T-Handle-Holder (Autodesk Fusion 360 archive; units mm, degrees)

design "T-Handle-Holder" references "Base"
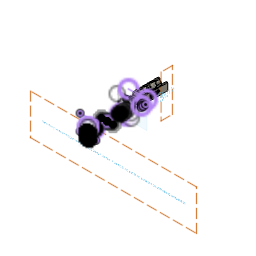
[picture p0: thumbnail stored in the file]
parameter "handle_width" = 30
parameter "stick_diameter" = 7
parameter "hole_bottom_diameter" = 17
parameter "end_front_diameter" = 23
parameter "end_back_diameter" = 25
parameter "stick_center_to_back_end_distance" = 50
parameter "stick_center_to_front_end_distance" = 50
parameter "bottom_hole_to_front_bottom_ditance" = 15
component_insert "Component Insert"
sketch "Reference" plane through (0, 55.6118, 0) normal (0, 1, 0) x axis (-1, 0, 0)
  line L1 (0, 47.0059) -> (0, -10)
  line L2 (-48, 47.0059) -> (0, 47.0059)
  line L3 (-48, -10) -> (-48, 47.0059)
  line L4 (0, -10) -> (-48, -10)
  line L5 (-48, 60) -> (0, 60)
sketch "Bottom" plane through (0, 0, 0) normal (0, 0, 1) x axis (1, 0, 0)
  circle C1 centre (0, 0) radius 8.5
  circle C2 centre (0, 0) radius 3.5
  point P1 (0, 0)
  point P2 (0, 0)
  point P3 (0, 0)
  coincident P1 P2
  coincident P1 P3
  dimension "d5" diameter C1 = 17 (= "hole_bottom_diameter")
  dimension "d6" diameter C2 = 7 (= "stick_diameter")
work_plane "WorkPlane1" sketch "Bottom" AlongDistance 15 (= "bottom_hole_to_front_bottom_ditance")
sketch "Center" plane through (0, 0, 15) normal (0, 0, 1) x axis (1, 0, 0)
  line L1 (0, -50) -> (0, 0)
  line L2 (0, 50) -> (0, 0)
  line L3 (0, -33) -> (0, 0)
  line L4 (0, 33) -> (0, 0)
  line L5 (-15, 0) -> (0, 0)
  curve K1 (0, 33) -> (0, -33)
  curve K2 (-4, -33) -> (4, -33)
  curve K3 (4, 33) -> (-4, 33)
  curve K4 (0, 33) -> (0, -33)
  curve K5 (4, -33) -> (-4, -33)
  curve K6 (-4, 33) -> (4, 33)
  circle C1 centre (0, 0) radius 15
  point P2 (0, 0)
  point P3 (0, 0)
  point P6 (0, 0)
  point P8 (0, 0)
  point P7 (0, -33)
  point P9 (0, 33)
  point P15 (0, -33)
  point P17 (0, 33)
  point P10 (-15, 0)
  point P16 (15, 0)
  point P11 (4, -33)
  point P18 (-4, -33)
  point P12 (-4, -33)
  point P19 (4, -33)
  point P13 (-4, 33)
  point P20 (4, 33)
  point P14 (4, 33)
  point P21 (-4, 33)
  point P4 (0, -50)
  point P5 (0, 50)
  coincident P2 P3
  vertical L1
  parallel L1 L2
  coincident P2 P6
  parallel L1 L3
  coincident P2 P8
  parallel L2 L4
  perpendicular L1 L5
  midpoint P7 K2
  midpoint P9 K3
  symmetric L1 P7 P15
  symmetric L1 P9 P17
  symmetric L1 P10 P16
  symmetric L1 P11 P18
  symmetric L1 P12 P19
  symmetric L1 P13 P20
  symmetric L1 P14 P21
  dimension "d13" distance P3 P4 = 50 (= "stick_center_to_front_end_distance")
  dimension "d14" distance P3 P5 = 50 (= "stick_center_to_back_end_distance")
  dimension "d19" diameter C1 = 30 (= "handle_width")
  dimension "d65" distance P3 P7 = 33 (= "stick_center_to_front_end_distance * 0.66")
  dimension "d66" distance P8 P9 = 33 (= "stick_center_to_back_end_distance * 0.66")
  dimension "d67" distance P3 P10 = 15 (= "handle_width / 2")
work_plane "WorkPlane2" AlongDistance -50
work_plane "WorkPlane3" AlongDistance 50
sketch "Front end" plane through (0, -50, 0) normal (0, 1, 0) x axis (1, 0, 0)
  circle C1 centre (0, -26.5) radius 11.5
  point P2 (0, -15)
  coincident P2 C1
  dimension "d17" diameter C1 = 23 (= "end_front_diameter")
sketch "Back end" plane through (0, 50, 0) normal (0, 1, 0) x axis (1, 0, 0)
  circle C1 centre (0, -27.5) radius 12.5
  point P2 (0, -15)
  coincident P2 C1
  dimension "d18" diameter C1 = 25 (= "end_back_diameter")
sketch "Holder dimensions" plane through (0, 50, 0) normal (0, 1, 0) x axis (1, 0, 0)
  line L1 (12.5, -27.5) -> (0, -27.5)
  line L2 (0, -2.5) -> (0, -20)
  line L3 (-12.5, -27.5) -> (0, -27.5)
  line L4 (0, -27.5) -> (0, -40)
  line L5 (0, -15) -> (0, -27.5)
  line L6 (-24, -40) -> (0, -40)
  line L7 (-12.5, -40) -> (-12.5, -27.5)
  line L8 (12.5, -3) -> (12.5, -27.5)
  line L9 (12, -15) -> (0, -15)
  line L10 (12.5, -40) -> (-12.5, -40)
  line L11 (12.5, -15) -> (12.5, -40)
  line L12 (-12.5, -15) -> (12.5, -15)
  line L13 (-12.5, -40) -> (-12.5, -15)
  line L14 (-20.5, -7) -> (20.5, -7)
  line L15 (-20.5, -48) -> (-20.5, -7)
  line L16 (20.5, -48) -> (-20.5, -48)
  line L17 (20.5, -7) -> (20.5, -48)
  line L18 (-20.5, -27.5) -> (20.5, -27.5)
  circle C1 centre (0, -27.5) radius 12.5
  point P2 (0, -27.5)
  point P3 (0, -27.5)
  point P4 (12.5, -27.5)
  point P7 (0, -27.5)
  point P8 (-12.5, -27.5)
  point P9 (0, -40)
  point P10 (0, -15)
  point P12 (-12.5, -40)
  point P16 (12.5, -15)
  point P22 (20.5, -27.5)
  point P23 (-20.5, -27.5)
  coincident P2 P3
  coincident C1 P4
  horizontal L1
  symmetric P3 L2 P7
  symmetric P4 L2 P8
  coincident C1 P9
  perpendicular L1 L4
  coincident L2 P10
  coincident C1 P10
  perpendicular L5 L6
  coincident L6 P12
  tangent C1 L7
  perpendicular L6 L7
  tangent C1 L8
  perpendicular L8 L9
  horizontal L10
  vertical L11
  horizontal L12
  vertical L13
  coincident L8 P16
  coincident L9 P16
  midpoint L17 P22
  midpoint L15 P23
  dimension "d20" = 8
extrude "Extrude1" new body sketch "Holder dimensions" + "Back end" profile of S2:C1 S1:C1 S1:L2 S1:L10 S1:L11 S1:L12 S1:L13 S1:L15 S1:L17 S1:L16 S1:L14 to an object
extrude "Extrude2" cut sketch "Back end" to an object
extrude "Extrude3" cut sketch "Front end" to an object
sketch "Sketch12" plane through (0, 0, 15) normal (0, 0, 1) x axis (1, 0, 0)
  curve K1 (0, 33) -> (0, -33)
  curve K2 (0, 33) -> (0, -33)
  line L1 (0, 33) -> (0, 50)
  line L2 (0, -50) -> (0, -33)
  curve K3 (0, 41.5) -> (-15, 0)
  curve K4 (3.7751, 41.8206) -> (-3.7751, 41.1794)
  curve K5 (0, -41.5) -> (-15, 0)
  curve K6 (4, -41.5) -> (-4, -41.5)
  curve K7 (0, -41.5) -> (15, 0)
  curve K8 (-15.1994, -6.2868) -> (-14.8006, 6.2868)
  curve K9 (15.1994, -6.2868) -> (14.8006, 6.2868)
  curve K10 (-4, -41.5) -> (4, -41.5)
  curve K11 (0, 41.5) -> (15, 0)
  curve K12 (-15.2215, 5.4019) -> (-14.7785, -5.4019)
  curve K13 (15.2215, 5.4019) -> (14.7785, -5.4019)
  curve K14 (-3.7751, 41.8206) -> (3.7751, 41.1794)
  point P3 (0, 33)
  point P7 (0, 33)
  point P2 (0, -33)
  point P8 (0, -33)
  point P10 (-15, 0)
  point P11 (0, 41.5)
  point P14 (0, -41.5)
  point P17 (15, 0)
  point P25 (0, 41.5)
  point P12 (-3.7751, 41.1794)
  point P30 (3.7751, 41.1794)
  point P13 (3.7751, 41.8206)
  point P31 (-3.7751, 41.8206)
  point P18 (0, -41.5)
  point P15 (-4, -41.5)
  point P23 (4, -41.5)
  point P16 (4, -41.5)
  point P24 (-4, -41.5)
  point P19 (-14.8006, 6.2868)
  point P21 (14.8006, 6.2868)
  point P20 (-15.1994, -6.2868)
  point P22 (15.1994, -6.2868)
  point P26 (-14.7785, -5.4019)
  point P28 (14.7785, -5.4019)
  point P27 (-15.2215, 5.4019)
  point P29 (15.2215, 5.4019)
  coincident P3 P7
  vertical L1
  coincident P2 P8
  parallel L1 L2
  coincident K1 P10
  midpoint L1 P11
  midpoint P11 K4
  midpoint L2 P14
  midpoint P14 K6
  midpoint P10 K8
  midpoint P10 K12
  symmetric L2 P10 P17
  symmetric L2 P11 P25
  symmetric L2 P12 P30
  symmetric L2 P13 P31
  symmetric L2 P14 P18
  symmetric L2 P15 P23
  symmetric L2 P16 P24
  symmetric L2 P19 P21
  symmetric L2 P20 P22
  symmetric L2 P26 P28
  symmetric L2 P27 P29
  coincident P15 P24
work_plane "WorkPlane4" sketch "Sketch12" AlongDistance 26.5
sketch "Sketch13" plane through (0, 0, 27.5) normal (0, 0, 1) x axis (1, 0, 0)
  curve K1 (0, 33) -> (0, -33)
  curve K2 (0, 33) -> (0, -33)
  curve K3 (0, 41.5) -> (15, 0)
  curve K4 (0, 41.5) -> (-15, 0)
  curve K5 (0, -41.5) -> (-15, 0)
  curve K6 (0, -41.5) -> (15, 0)
loft "Loft2" sketch "Bottom" + "Sketch13"
sketch "Remove shit" plane through (0, -50, 0) normal (0, -1, 0) x axis (1, 0, 0)
  line L1 (20.5, 7) -> (-20.5, 7)
  line L2 (20.5, 48) -> (20.5, 7)
  line L3 (-20.5, 48) -> (20.5, 48)
  line L4 (-20.5, 7) -> (-20.5, 48)
  line L5 (-3.5, 0) -> (3.5, 0)
  line L6 (-3.5, 15.5455) -> (-3.5, 0)
  line L7 (3.5, 15.5455) -> (3.5, 0)
  line L8 (20.5, 27.5) -> (-20.5, 27.5)
  circle C1 centre (0, 26.5) radius 11.5
  circle C2 centre (0, 26.5) radius 11.5
  point P8 (-3.5, 0)
  point P10 (-3.5, 0)
  point P11 (-3.5, 15.5455)
  point P7 (3.5, 0)
  point P12 (3.5, 0)
  point P13 (3.5, 15.5455)
  point P14 (-20.5, 27.5)
  point P15 (20.5, 27.5)
  coincident P8 P10
  coincident C1 P11
  perpendicular L5 L6
  coincident P7 P12
  coincident C2 P13
  perpendicular L5 L7
  midpoint L4 P14
  midpoint L2 P15
extrude "Extrude4" cut sketch "Remove shit" profile of C1 L1 C2 L6 L7 to an object
extrude "Extrude8" cut sketch "Remove shit" profile of C1 L2 L3 L4 C2 L8 to an object
extrude "Extrude6" cut sketch "Center" profile of C1 along normal blind 200
extrude "Extrude7" add sketch "Holder dimensions" profile of C1 L2 L11 L12 L13 L15 L17 L14 L18 along normal blind 10
extrude "Extrude12" add of existing geometry blind 10
fillet "Fillet6" radius 1
move "Move1"
move "Move2"
extrude "Extrude9" new body of existing geometry blind 20
extrude "Extrude10" add of existing geometry blind 50
extrude "Extrude11" cut of existing geometry to an object
sketch "Text" plane through (44.5, 0, 0) normal (1, 0, 0) x axis (0, 1, 0)
  line L1 (48.9918, 52.4859) -> (55.6118, 52.4859)
  line L2 (48.9918, 53.9359) -> (48.9918, 52.4859)
  line L3 (44.7318, 53.9359) -> (48.9918, 53.9359)
  line L4 (44.7318, 50.6559) -> (44.7318, 53.9359)
  line L5 (44.7318, 45.6759) -> (44.7318, 48.9559)
  line L6 (48.9918, 45.6759) -> (44.7318, 45.6759)
  line L7 (48.9918, 47.1259) -> (48.9918, 45.6759)
  line L8 (55.6118, 47.1259) -> (48.9918, 47.1259)
  curve K1
  curve K2
  curve K3
  curve K4
  line L9 (55.6118, 52.4859) -> (55.6118, 47.1259)
  arc A1 centre (44.7318, 49.8059) radius 0.85 clockwise from (44.7318, 50.6559) to (44.7318, 48.9559)
  dimension "d61" Text1-Height = 3
extrude "Extrude13" cut sketch "Text" against normal blind 2
sketch "Filename" plane through (0, 0, 0) normal (0, 1, 0) x axis (1, 0, 0)
  dimension "d64" = 5
fillet "Fillet11" radius 5
fillet "Fillet12" radius 3
extrude "Extrude14" cut of existing geometry to an object
scale "Scale1"
move "Move3"
extrude "Extrude15" new body of existing geometry blind 20
extrude "Extrude16" add of existing geometry to an object
extrude "Extrude17" cut of existing geometry to an object

design "Base"
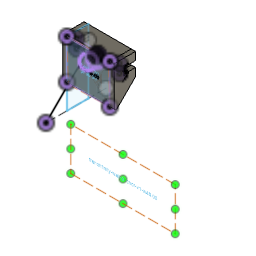
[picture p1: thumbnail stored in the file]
parameter "wall_anchor_height" = 60
parameter "wall_anchor_width" = 20
parameter "wall_anchor_angle" = 45
parameter "width_per_slot" = 40
parameter "slot_inner_width" = 8.5
parameter "slot_inner_height" = 4.5
parameter "slot_outer_width" = 5.6
parameter "slot_outer_height" = 6.5
parameter "slot_dept" = 15
parameter "print_tolerance" = 0.12
parameter "base_plate_thickness" = 16
parameter "base_plate_slot_height" = 50
parameter "wall_anchor_angle_rounded_border" = 1.5
parameter "base_plate_screw_hole_diameter" = 4
parameter "base_plate_screw_head_diameter" = 8
parameter "base_plate_screw_head_height" = 4
parameter "base_plate_screw_hole_side_distance" = 7
parameter "slot_screw_head_width" = 4.42 (= "4.3 mm + print_tolerance")
parameter "slot_screw_thread_width" = 2.12 (= "2 mm + print_tolerance")
parameter "slot_screw_head_height" = 2.12 (= "2 mm + print_tolerance")
parameter "width" = 48
parameter "filament_hole_width" = 1.7
parameter "plate_height" = 50
sketch "Side" plane through (0, 0, 0) normal (1, 0, 0) x axis (0, 1, 0)
  line L1 (39.6118, 0) -> (19.6118, 0)
  line L2 (39.6118, 60) -> (39.6118, 0)
  line L3 (19.6118, 60) -> (39.6118, 60)
  line L4 (19.6118, 0) -> (19.6118, 60)
  line L5 (39.6118, 39.6118) -> (0, 0)
  line L6 (56.0196, 0) -> (0, 0)
  point P1 (0, 0)
  point P6 (0, 0)
  point P7 (39.6118, 39.6118)
  point P2 (19.6118, 0)
  point P3 (39.6118, 0)
  point P5 (19.6118, 60)
  horizontal L1
  vertical L2
  horizontal L3
  vertical L4
  horizontal L6
  coincident P1 P6
  coincident L2 P7
  dimension "d4" distance P2 P3 = 20 (= "wall_anchor_width")
  dimension "d5" distance P2 P5 = 60 (= "wall_anchor_height")
  dimension "d6" angle L5 L6 = 45 (= "wall_anchor_angle")
extrude "Extrude1" new body sketch "Side" profile of L1 L2 L3 L4 L5 along normal blind 40 (= "width_per_slot")
sketch "Slot LeftToRight" plane through (0, 0, 0) normal (-1, 0, 0) x axis (0, -1, 0)
  line L1 (-19.6118, 60) -> (-19.6118, 19.6118)
  line L2 (-39.6118, 60) -> (-19.6118, 60)
  line L3 (-39.6118, 39.6118) -> (-39.6118, 60)
  line L4 (-19.6118, 19.6118) -> (-39.6118, 39.6118)
  line L5 (-39.6118, 52.6059) -> (-39.6118, 49.8059)
  line L6 (-39.6118, 47.0059) -> (-39.6118, 49.8059)
  line L7 (-33.1118, 52.6059) -> (-39.6118, 52.6059)
  line L8 (-28.6118, 49.8059) -> (-39.6118, 49.8059)
  line L9 (-28.6118, 54.0559) -> (-28.6118, 49.8059)
  line L10 (-33.1118, 54.0559) -> (-28.6118, 54.0559)
  line L11 (-33.1118, 52.6059) -> (-33.1118, 54.0559)
  line L12 (-28.6118, 45.5559) -> (-28.6118, 49.8059)
  line L13 (-33.1118, 45.5559) -> (-28.6118, 45.5559)
  line L14 (-33.1118, 47.0059) -> (-33.1118, 45.5559)
  line L15 (-33.1118, 47.0059) -> (-39.6118, 47.0059)
  point P6 (-39.6118, 49.8059)
  point P7 (-39.6118, 52.6059)
  point P17 (-39.6118, 47.0059)
  point P9 (-33.1118, 52.6059)
  point P16 (-33.1118, 47.0059)
  point P10 (-28.6118, 49.8059)
  point P13 (-28.6118, 49.8059)
  point P11 (-28.6118, 54.0559)
  point P14 (-28.6118, 45.5559)
  point P12 (-33.1118, 54.0559)
  point P15 (-33.1118, 45.5559)
  midpoint L3 P6
  parallel L3 L5
  parallel L3 L6
  perpendicular L3 L7
  perpendicular L6 L8
  perpendicular L8 L9
  perpendicular L9 L10
  symmetric P7 L8 P17
  symmetric P9 L8 P16
  symmetric P10 L8 P13
  symmetric L8 P11 P14
  symmetric L8 P12 P15
  dimension "d80" distance P6 P7 = 2.8 (= "slot_outer_width / 2")
  dimension "d82" distance P7 P9 = 6.5 (= "slot_outer_height")
  dimension "d84" distance P6 P10 = 11 (= "slot_outer_height + slot_inner_height")
  dimension "d85" distance P10 P11 = 4.25 (= "slot_inner_width / 2")
  dimension "d86" distance P11 P12 = 4.5 (= "slot_inner_height")
extrude "Extrude3" cut sketch "Slot LeftToRight" profile of L3 L5 L6 L7 L9 L10 L11 L12 L13 L14 L15 against normal blind 40 (magnitude of "width_per_slot * -1")
sketch "Plate" plane through (0, 39.6118, 0) normal (0, 1, 0) x axis (-1, 0, 0)
  line L1 (0, 39.6118) -> (-40, 39.6118)
  line L2 (-40, 60) -> (0, 60)
  line L3 (0, 10) -> (0, 60)
  line L4 (-40, 10) -> (-40, 60)
  line L5 (-40, 10) -> (0, 10)
  line L6 (-40, 47.0059) -> (0, 47.0059)
  line L7 (-40, 52.6059) -> (-40, 60)
  line L8 (0, 60) -> (0, 52.6059)
  line L9 (0, 52.6059) -> (-40, 52.6059)
  line L10 (-40, 60) -> (0, 60)
  line L11 (-40, 39.6118) -> (-40, 47.0059)
  line L12 (0, 47.0059) -> (0, 39.6118)
  point P2 (0, 60)
  point P3 (-40, 60)
  point P4 (0, 10)
  point P5 (-40, 10)
  perpendicular L1 L3
  perpendicular L1 L4
  dimension "d36" distance P2 P3 = 40 (= "width_per_slot")
  dimension "d37" distance P2 P4 = 50 (= "base_plate_slot_height")
  dimension "d39" distance P3 P5 = 50 (= "base_plate_slot_height")
extrude "Extrude6" new body sketch "Plate" profile of L1 L2 L3 L4 L5 L6 L7 L8 L9 L10 along normal blind 16 (= "base_plate_thickness") bodies "Base plate with slot"
sketch "Slot" plane through (0, 0, 0) normal (-1, 0, 0) x axis (0, -1, 0)
  line L1 (-19.6118, 60) -> (-19.6118, 19.6118)
  line L2 (-39.6118, 60) -> (-19.6118, 60)
  line L3 (-39.6118, 52.6059) -> (-39.6118, 60)
  line L4 (-33.1118, 52.6059) -> (-39.6118, 52.6059)
  line L5 (-33.1118, 54.0559) -> (-33.1118, 52.6059)
  line L6 (-28.6118, 54.0559) -> (-33.1118, 54.0559)
  line L7 (-28.6118, 45.5559) -> (-28.6118, 54.0559)
  line L8 (-33.1118, 45.5559) -> (-28.6118, 45.5559)
  line L9 (-33.1118, 47.0059) -> (-33.1118, 45.5559)
  line L10 (-39.6118, 47.0059) -> (-33.1118, 47.0059)
  line L11 (-39.6118, 39.6118) -> (-39.6118, 47.0059)
  line L12 (-19.6118, 19.6118) -> (-39.6118, 39.6118)
  line L13 (-33.1118, 52.6059) -> (-39.6118, 52.6059)
  line L14 (-33.1118, 54.0559) -> (-33.1118, 52.6059)
  line L15 (-28.6118, 54.0559) -> (-33.1118, 54.0559)
  line L16 (-28.6118, 45.5559) -> (-28.6118, 54.0559)
  line L17 (-33.1118, 45.5559) -> (-28.6118, 45.5559)
  line L18 (-33.1118, 47.0059) -> (-33.1118, 45.5559)
  line L19 (-39.6118, 47.0059) -> (-33.1118, 47.0059)
  line L20 (-39.6118, 10) -> (-39.6118, 60)
  line L21 (-32.9918, 52.4859) -> (-39.6118, 52.4859)
  line L22 (-32.9918, 53.9359) -> (-32.9918, 52.4859)
  line L23 (-28.7318, 53.9359) -> (-32.9918, 53.9359)
  line L24 (-28.7318, 45.6759) -> (-28.7318, 53.9359)
  line L25 (-32.9918, 45.6759) -> (-28.7318, 45.6759)
  line L26 (-32.9918, 47.1259) -> (-32.9918, 45.6759)
  line L27 (-39.6118, 47.1259) -> (-32.9918, 47.1259)
  line L28 (-33.1118, 52.6059) -> (-39.6118, 52.6059)
  line L29 (-33.1118, 52.6059) -> (-33.1118, 54.0559)
  line L30 (-28.6118, 54.0559) -> (-33.1118, 54.0559)
  line L31 (-28.6118, 45.5559) -> (-28.6118, 54.0559)
  line L32 (-33.1118, 45.5559) -> (-28.6118, 45.5559)
  line L33 (-33.1118, 47.0059) -> (-33.1118, 45.5559)
  line L34 (-39.6118, 47.0059) -> (-33.1118, 47.0059)
  line L35 (-39.6118, 47.0059) -> (-39.6118, 52.6059)
  line L36 (-49.1118, 52.6059) -> (-55.6118, 52.6059)
  line L37 (-49.1118, 52.6059) -> (-49.1118, 54.0559)
  line L38 (-44.6118, 54.0559) -> (-49.1118, 54.0559)
  line L39 (-44.6118, 45.5559) -> (-44.6118, 54.0559)
  line L40 (-49.1118, 45.5559) -> (-44.6118, 45.5559)
  line L41 (-49.1118, 47.0059) -> (-49.1118, 45.5559)
  line L42 (-55.6118, 47.0059) -> (-49.1118, 47.0059)
  line L43 (-55.6118, 47.0059) -> (-55.6118, 52.6059)
  point P15 (-39.6118, 52.6059)
  point P33 (-39.6118, 52.6059)
  point P16 (-33.1118, 52.6059)
  point P34 (-33.1118, 52.6059)
  point P17 (-33.1118, 54.0559)
  point P35 (-33.1118, 54.0559)
  point P36 (-33.1118, 52.6059)
  point P18 (-28.6118, 54.0559)
  point P37 (-28.6118, 54.0559)
  point P19 (-28.6118, 45.5559)
  point P38 (-28.6118, 45.5559)
  point P10 (-28.6118, 45.5559)
  point P39 (-28.6118, 45.5559)
  point P11 (-33.1118, 45.5559)
  point P40 (-33.1118, 45.5559)
  point P41 (-33.1118, 45.5559)
  point P12 (-33.1118, 47.0059)
  point P42 (-33.1118, 47.0059)
  point P21 (-33.1118, 47.0059)
  point P43 (-33.1118, 47.0059)
  point P22 (-39.6118, 47.0059)
  point P44 (-39.6118, 47.0059)
  point P45 (-39.6118, 52.6059)
  point P46 (-39.6118, 47.0059)
  coincident P15 P33
  coincident P16 P34
  coincident P17 P35
  coincident P16 P36
  coincident P18 P37
  coincident P19 P38
  coincident P10 P39
  coincident P11 P40
  coincident P11 P41
  coincident P12 P42
  coincident P21 P43
  coincident P22 P44
  coincident P15 P45
  coincident P22 P46
  dimension "d91" = 0.12 (= "print_tolerance")
  dimension "d96" R-Pattern1-uDistance = -16 (= "base_plate_thickness * -1")
  dimension "d97" R-Pattern1-vDistance = 0
extrude "Extrude7" add sketch "Slot" profile of L20 L24 L23 L27 L22 L25 L26 L21 against normal blind 40 (magnitude of "width_per_slot * -1")
extrude "Extrude8" cut sketch "Slot" profile of L36 L37 L38 L39 L40 L41 L42 L43 no distance stored
sketch "Sketch3" plane through (0, 0, 0) normal (-1, 0, 0) x axis (0, -1, 0)
  line L1 (-32.9918, 47.1259) -> (-39.6118, 47.1259)
  line L2 (-32.9918, 45.6759) -> (-32.9918, 47.1259)
  line L3 (-28.7318, 45.6759) -> (-32.9918, 45.6759)
  line L4 (-28.7318, 53.9359) -> (-28.7318, 45.6759)
  line L5 (-32.9918, 53.9359) -> (-28.7318, 53.9359)
  line L6 (-32.9918, 52.4859) -> (-32.9918, 53.9359)
  line L7 (-39.6118, 52.4859) -> (-32.9918, 52.4859)
  line L8 (-44.6118, 45.5559) -> (-44.6118, 54.0559)
  line L9 (-32.9918, 52.4859) -> (-39.6118, 52.4859)
  line L10 (-32.9918, 53.9359) -> (-32.9918, 52.4859)
  line L11 (-28.7318, 53.9359) -> (-32.9918, 53.9359)
  line L12 (-28.7318, 45.6759) -> (-28.7318, 53.9359)
  line L13 (-32.9918, 45.6759) -> (-28.7318, 45.6759)
  line L14 (-32.9918, 47.1259) -> (-32.9918, 45.6759)
  line L15 (-39.6118, 47.1259) -> (-32.9918, 47.1259)
  line L16 (-39.6118, 47.1259) -> (-39.6118, 52.4859)
  line L17 (-55.6118, 52.4859) -> (-48.9918, 52.4859)
  line L18 (-48.9918, 52.4859) -> (-48.9918, 53.9359)
  line L19 (-48.9918, 53.9359) -> (-44.7318, 53.9359)
  line L20 (-44.7318, 45.6759) -> (-44.7318, 53.9359)
  line L21 (-48.9918, 45.6759) -> (-44.7318, 45.6759)
  line L22 (-48.9918, 47.1259) -> (-48.9918, 45.6759)
  line L23 (-55.6118, 47.1259) -> (-48.9918, 47.1259)
  line L24 (-55.6118, 47.1259) -> (-55.6118, 52.4859)
  line L25 (-55.6118, 47.0059) -> (-49.1118, 47.0059)
  line L26 (-55.6118, 10) -> (-55.6118, 47.0059)
  line L27 (-39.6118, 10) -> (-55.6118, 10)
  line L28 (-39.6118, 47.1259) -> (-39.6118, 10)
  line L29 (-39.6118, 60) -> (-39.6118, 52.4859)
  line L30 (-55.6118, 60) -> (-39.6118, 60)
  line L31 (-55.6118, 52.6059) -> (-55.6118, 60)
  line L32 (-49.1118, 52.6059) -> (-55.6118, 52.6059)
  line L33 (-49.1118, 54.0559) -> (-49.1118, 52.6059)
  line L34 (-44.6118, 54.0559) -> (-49.1118, 54.0559)
  line L35 (-49.1118, 45.5559) -> (-44.6118, 45.5559)
  line L36 (-49.1118, 47.0059) -> (-49.1118, 45.5559)
  point P9 (-39.6118, 52.4859)
  point P20 (-39.6118, 52.4859)
  point P19 (-39.6118, 47.1259)
  point P21 (-39.6118, 47.1259)
  coincident P9 P20
  coincident P19 P21
  dimension "d105" R-Pattern1-vDistance = 0
extrude "Extrude3" new body sketch "Sketch3" profile of L17 L18 L19 L20 L21 L22 L23 L24 against normal blind 40 (magnitude of "width_per_slot * -1")
sketch "Screw hole" plane through (0, 28.6118, 0) normal (0, 1, 0) x axis (-1, 0, 0)
  line L1 (0, 54.0559) -> (0, 45.5559)
  line L2 (-40, 54.0559) -> (0, 54.0559)
  line L3 (-40, 45.5559) -> (-40, 54.0559)
  line L4 (0, 45.5559) -> (-40, 45.5559)
  line L5 (0, 45.5559) -> (-40, 54.0559)
  line L6 (-40, 45.5559) -> (0, 54.0559)
  circle C1 centre (-20, 49.8059) radius 2.21
  circle C2 centre (-20, 49.8059) radius 1.06
  point P4 (-40, 54.0559)
  point P6 (-40, 54.0559)
  point P2 (0, 45.5559)
  point P7 (0, 45.5559)
  point P3 (0, 54.0559)
  point P8 (0, 54.0559)
  point P5 (-40, 45.5559)
  point P9 (-40, 45.5559)
  point P10 (-20, 49.8059)
  coincident P4 P6
  coincident P2 P7
  coincident P3 P8
  coincident P5 P9
  midpoint L5 P10
  concentric C1 C2
  dimension "d119" diameter C1 = 4.42 (= "slot_screw_head_width")
  dimension "d120" diameter C2 = 2.12 (= "slot_screw_thread_width")
extrude "Extrude4" cut sketch "Screw hole" profile of C2 against normal blind 2000
extrude "Extrude5" cut sketch "Screw hole" profile of C1 C2 no distance stored
fillet "Fillet1" radius 1.5 (= "wall_anchor_angle_rounded_border")
work_plane "WorkPlane1" sketch "Slot LeftToRight" AlongDistance -20 (= "-width_per_slot / 2")
sketch "Screw head" plane through (20, 0, 0) normal (-1, 0, 0) x axis (0, -1, 0)
  line L1 (-28.6118, 52.0159) -> (-28.6118, 47.5959)
  line L2 (-26.4918, 52.0159) -> (-26.4918, 47.5959)
  line L3 (-26.4918, 48.7459) -> (-26.4918, 50.8659)
  line L4 (-26.4918, 50.8659) -> (-28.6118, 52.0159)
  line L5 (-26.4918, 52.0159) -> (-28.6118, 52.0159)
  point P3 (-28.6118, 52.0159)
  point P8 (-28.6118, 52.0159)
  point P6 (-26.4918, 50.8659)
  point P9 (-26.4918, 50.8659)
  point P10 (-28.6118, 52.0159)
  point P5 (-26.4918, 52.0159)
  point P11 (-26.4918, 52.0159)
  coincident P3 P8
  coincident P6 P9
  coincident P3 P10
  coincident P5 P11
revolve "Revolve1" sketch "Screw head" AlongAngle 360
sketch "Plate" plane through (0, 39.6118, 0) normal (0, 1, 0) x axis (-1, 0, 0)
  line L1 (0, 39.6118) -> (-40, 39.6118)
  line L2 (-40, 60) -> (0, 60)
  line L3 (0, 10) -> (0, 60)
  line L4 (-40, 10) -> (-40, 60)
  line L5 (-40, 10) -> (0, 10)
  line L6 (-40, 47.0059) -> (0, 47.0059)
  line L7 (-40, 39.6118) -> (-40, 47.0059)
  line L8 (0, 47.0059) -> (0, 39.6118)
  line L9 (0, 52.6059) -> (-40, 52.6059)
  line L10 (-40, 60) -> (0, 60)
  line L11 (0, 60) -> (0, 52.6059)
  line L12 (-40, 52.6059) -> (-40, 60)
  point P2 (0, 60)
  point P3 (-40, 60)
  point P4 (0, 10)
  point P5 (-40, 10)
  perpendicular L1 L3
  perpendicular L1 L4
  dimension "d36_1" distance P2 P3 = 40 (= "width_per_slot")
  dimension "d37_1" distance P2 P4 = 50 (= "base_plate_slot_height")
  dimension "d39_1" distance P3 P5 = 50 (= "base_plate_slot_height")
extrude "Extrude6" new body sketch "Plate" profile of L1 L2 L3 L4 L5 L6 L7 L8 L9 L10 along normal blind 16 (= "base_plate_thickness") named "d89_1" bodies "Base plate with slot"
sketch "Slot" plane through (0, 0, 0) normal (-1, 0, 0) x axis (0, -1, 0)
  line L1 (-19.6118, 60) -> (-19.6118, 23.2332)
  line L2 (-39.6118, 60) -> (-19.6118, 60)
  line L3 (-39.6118, 52.6059) -> (-39.6118, 60)
  line L4 (-33.1118, 52.6059) -> (-39.6118, 52.6059)
  line L5 (-33.1118, 54.0559) -> (-33.1118, 52.6059)
  line L6 (-28.6118, 54.0559) -> (-33.1118, 54.0559)
  line L7 (-28.6118, 45.5559) -> (-28.6118, 54.0559)
  line L8 (-33.1118, 45.5559) -> (-28.6118, 45.5559)
  line L9 (-33.1118, 47.0059) -> (-33.1118, 45.5559)
  line L10 (-39.6118, 47.0059) -> (-33.1118, 47.0059)
  line L11 (-39.6118, 39.6118) -> (-39.6118, 47.0059)
  line L12 (-22.1725, 22.1725) -> (-39.6118, 39.6118)
  line L13 (-33.1118, 52.6059) -> (-39.6118, 52.6059)
  line L14 (-33.1118, 54.0559) -> (-33.1118, 52.6059)
  line L15 (-28.6118, 54.0559) -> (-33.1118, 54.0559)
  line L16 (-28.6118, 45.5559) -> (-28.6118, 54.0559)
  line L17 (-33.1118, 45.5559) -> (-28.6118, 45.5559)
  line L18 (-33.1118, 47.0059) -> (-33.1118, 45.5559)
  line L19 (-39.6118, 47.0059) -> (-33.1118, 47.0059)
  line L20 (-39.6118, 10) -> (-39.6118, 60)
  line L21 (-32.9918, 52.4859) -> (-39.6118, 52.4859)
  line L22 (-32.9918, 53.9359) -> (-32.9918, 52.4859)
  line L23 (-28.7318, 53.9359) -> (-32.9918, 53.9359)
  line L24 (-28.7318, 45.6759) -> (-28.7318, 53.9359)
  line L25 (-32.9918, 45.6759) -> (-28.7318, 45.6759)
  line L26 (-32.9918, 47.1259) -> (-32.9918, 45.6759)
  line L27 (-39.6118, 47.1259) -> (-32.9918, 47.1259)
  line L28 (-33.1118, 52.6059) -> (-39.6118, 52.6059)
  line L29 (-33.1118, 52.6059) -> (-33.1118, 54.0559)
  line L30 (-28.6118, 54.0559) -> (-33.1118, 54.0559)
  line L31 (-28.6118, 45.5559) -> (-28.6118, 54.0559)
  line L32 (-33.1118, 45.5559) -> (-28.6118, 45.5559)
  line L33 (-33.1118, 47.0059) -> (-33.1118, 45.5559)
  line L34 (-39.6118, 47.0059) -> (-33.1118, 47.0059)
  line L35 (-39.6118, 47.0059) -> (-39.6118, 52.6059)
  line L36 (-49.1118, 52.6059) -> (-55.6118, 52.6059)
  line L37 (-49.1118, 52.6059) -> (-49.1118, 54.0559)
  line L38 (-44.6118, 54.0559) -> (-49.1118, 54.0559)
  line L39 (-44.6118, 45.5559) -> (-44.6118, 54.0559)
  line L40 (-49.1118, 45.5559) -> (-44.6118, 45.5559)
  line L41 (-49.1118, 47.0059) -> (-49.1118, 45.5559)
  line L42 (-55.6118, 47.0059) -> (-49.1118, 47.0059)
  line L43 (-55.6118, 47.0059) -> (-55.6118, 52.6059)
  arc A1 centre (-21.1118, 23.2332) radius 1.5 clockwise from (-19.6118, 23.2332) to (-22.1725, 22.1725)
  point P15 (-39.6118, 52.6059)
  point P33 (-39.6118, 52.6059)
  point P16 (-33.1118, 52.6059)
  point P34 (-33.1118, 52.6059)
  point P17 (-33.1118, 54.0559)
  point P35 (-33.1118, 54.0559)
  point P36 (-33.1118, 52.6059)
  point P18 (-28.6118, 54.0559)
  point P37 (-28.6118, 54.0559)
  point P19 (-28.6118, 45.5559)
  point P38 (-28.6118, 45.5559)
  point P10 (-28.6118, 45.5559)
  point P39 (-28.6118, 45.5559)
  point P11 (-33.1118, 45.5559)
  point P40 (-33.1118, 45.5559)
  point P41 (-33.1118, 45.5559)
  point P12 (-33.1118, 47.0059)
  point P42 (-33.1118, 47.0059)
  point P21 (-33.1118, 47.0059)
  point P43 (-33.1118, 47.0059)
  point P22 (-39.6118, 47.0059)
  point P44 (-39.6118, 47.0059)
  point P45 (-39.6118, 52.6059)
  point P46 (-39.6118, 47.0059)
  coincident P15 P33
  coincident P16 P34
  coincident P17 P35
  coincident P16 P36
  coincident P18 P37
  coincident P19 P38
  coincident P10 P39
  coincident P11 P40
  coincident P11 P41
  coincident P12 P42
  coincident P21 P43
  coincident P22 P44
  coincident P15 P45
  coincident P22 P46
  dimension "d91_1" = 0.12 (= "print_tolerance")
  dimension "d96_1" R-Pattern1-uDistance = -16 (= "base_plate_thickness * -1")
  dimension "d97_1" R-Pattern1-vDistance = 0
extrude "Extrude8" cut sketch "Slot" profile of L36 L37 L38 L39 L40 L41 L42 L43 no distance stored
sketch "Screw" plane through (0, 55.6118, 0) normal (0, 1, 0) x axis (-1, 0, 0)
  line L1 (-40, 47.0059) -> (0, 47.0059)
  line L2 (-40, 10) -> (-40, 47.0059)
  line L3 (0, 10) -> (-40, 10)
  line L4 (0, 47.0059) -> (0, 10)
  line L5 (-33, 17) -> (-33, 40.0059)
  line L6 (-7, 17) -> (-33, 17)
  line L7 (-7, 40.0059) -> (-7, 17)
  line L8 (-33, 40.0059) -> (-7, 40.0059)
  circle C1 centre (-33, 17) radius 4
  circle C2 centre (-33, 17) radius 2
  point P7 (-33, 17)
  point P10 (-33, 17)
  coincident P7 P10
  concentric C1 C2
  dimension "d127" = -7 (= "base_plate_screw_hole_side_distance * -1")
  dimension "d128" diameter C1 = 8
  dimension "d129" diameter C2 = 4
rectangular_pattern "R-Pattern2" countU 1 (= "floor(( width / mm ) / ( width_per_slot / cm * 10 ))") uSpaceDistance 40 (= "width_per_slot") vSpaceDistance 0
work_plane "WorkPlane2"
extrude "Extrude12" new body of existing geometry no distance stored
mirror "Mirror3" mirrorStitchTolerance 0.1
sketch "filename" plane through (0, 19.6118, 0) normal (0, -1, 0) x axis (1, 0, 0)
  dimension "d216" = 3
sketch "Text" plane through (0, 19.6118, 0) normal (0, -1, 0) x axis (1, 0, 0)
  line L1 (44, 60) -> (44, 23.2332)
  line L2 (40, 23.2332) -> (40, 60)
  line L3 (44, 23.2332) -> (40, 23.2332)
  line L4 (44, 60) -> (44, 23.2332)
  line L5 (40, 60) -> (44, 60)
  line L6 (0, 60) -> (0, 23.2332)
  line L7 (-4, 60) -> (0, 60)
  line L8 (-4, 23.2332) -> (-4, 60)
  line L9 (0, 23.2332) -> (-4, 23.2332)
  curve K1
  curve K2
  curve K3
  curve K4
  line L10 (80, 60) -> (40, 60)
  point P4 (44, 23.2332)
  point P2 (-4, 60)
  coincident P4
  coincident P2
  parallel K3 L10
  dimension "d229" Text1-Height = 3
extrude "Extrude19" cut sketch "Text" against normal blind 2
extrude "Extrude14" cut of existing geometry blind 4 (= "( width_per_slot - width ) / -2")
extrude "Extrude15" cut of existing geometry blind 4 (= "( width_per_slot - width ) / -2")
extrude "Extrude9" cut of existing geometry blind -39 (= "-width_per_slot + 1 mm")
extrude "Extrude10" add of existing geometry blind 47 (= "width - 1 mm")
extrude "Extrude13" cut of existing geometry blind -30
extrude "Extrude14" add of existing geometry blind 50 (= "plate_height")
sketch "Sketch7" plane through (0, 39.6118, 0) normal (0, -1, 0) x axis (1, 0, 0)
  dimension "d236" = 3
extrude "Extrude11" cut sketch "Sketch7" against normal blind 2
sketch "File name" plane through (0, 39.6118, 0) normal (0, -1, 0) x axis (1, 0, 0)
  line L1 (18.0624, 22.4163) -> (17.825, 22.4163)
  line L2 (18.0624, 19.404) -> (18.0624, 22.4163)
  line L3 (17.6941, 19.404) -> (18.0624, 19.404)
  line L4 (17.6941, 21.7512) -> (17.6941, 19.404)
  curve K1 (17.3441, 21.4975) -> (17.6941, 21.7512)
  curve K2 (16.9574, 21.3072) -> (17.3441, 21.4975)
  line L5 (16.9574, 21.6632) -> (16.9574, 21.3072)
  curve K3 (17.4976, 22.0152) -> (16.9574, 21.6632)
  curve K4 (17.825, 22.4163) -> (17.4976, 22.0152)
  line L6 (21.2896, 19.404) -> (21.7295, 21.0759)
  line L7 (20.9048, 19.404) -> (21.2896, 19.404)
  line L8 (20.2398, 21.5773) -> (20.9048, 19.404)
  line L9 (20.6204, 21.5773) -> (20.2398, 21.5773)
  line L10 (20.9662, 20.3228) -> (20.6204, 21.5773)
  line L11 (21.0952, 19.8563) -> (20.9662, 20.3228)
  curve K5 (21.2077, 20.3044) -> (21.0952, 19.8563)
  line L12 (21.5535, 21.5773) -> (21.2077, 20.3044)
  line L13 (21.9321, 21.5773) -> (21.5535, 21.5773)
  line L14 (22.2575, 20.3167) -> (21.9321, 21.5773)
  line L15 (22.366, 19.9013) -> (22.2575, 20.3167)
  line L16 (22.4908, 20.3208) -> (22.366, 19.9013)
  line L17 (22.8632, 21.5773) -> (22.4908, 20.3208)
  line L18 (23.2213, 21.5773) -> (22.8632, 21.5773)
  line L19 (22.542, 19.404) -> (23.2213, 21.5773)
  line L20 (22.1593, 19.404) -> (22.542, 19.404)
  line L21 (21.8134, 20.7055) -> (22.1593, 19.404)
  line L22 (21.7295, 21.0759) -> (21.8134, 20.7055)
  line L23 (20.0965, 20.3044) -> (20.0965, 20.6748)
  line L24 (18.9649, 20.3044) -> (20.0965, 20.3044)
  line L25 (18.9649, 20.6748) -> (18.9649, 20.3044)
  line L26 (20.0965, 20.6748) -> (18.9649, 20.6748)
  line L27 (15.6293, 19.404) -> (16.4519, 21.5773)
  line L28 (15.2855, 19.404) -> (15.6293, 19.404)
  line L29 (14.4587, 21.5773) -> (15.2855, 19.404)
  line L30 (14.8475, 21.5773) -> (14.4587, 21.5773)
  line L31 (15.3141, 20.2758) -> (14.8475, 21.5773)
  curve K6 (15.4533, 19.8379) -> (15.3141, 20.2758)
  curve K7 (15.5904, 20.2512) -> (15.4533, 19.8379)
  line L32 (16.0733, 21.5773) -> (15.5904, 20.2512)
  line L33 (16.4519, 21.5773) -> (16.0733, 21.5773)
  line L34 (0, 47.1259) -> (48, 47.1259)
  line L35 (0, -10) -> (0, 47.1259)
  line L36 (48, 47.1259) -> (48, -10)
  curve K8
  curve K9
  curve K10
  curve K11
  curve K12 (25.8755, 21.6428) -> (25.986, 21.2703)
  line L37 (48, -10) -> (0, -10)
  line L38 (24.6088, 20.1223) -> (24.6088, 19.404)
  curve K13 (25.986, 21.2703) -> (26.3257, 21.0309)
  curve K14 (27.4594, 19.6148) -> (27.7316, 20.2615)
  curve K15 (29.6879, 22.2403) -> (29.3625, 21.7389)
  line L39 (23.3073, 20.1223) -> (24.6088, 20.1223)
  curve K16 (25.368, 17.3556) -> (25.0672, 17.6359)
  curve K17 (25.5542, 16.9095) -> (25.368, 17.3556)
  curve K18 (19.7404, 16.5411) -> (20.0495, 16.6271)
  curve K19 (22.2984, 14.9736) -> (21.9199, 15.1148)
  curve K20 (30.2323, 22.4163) -> (29.6879, 22.2403)
  curve K21 (30.6559, 22.3181) -> (30.2323, 22.4163)
  curve K22 (30.9567, 22.0377) -> (30.6559, 22.3181)
  curve K23 (31.1429, 21.5916) -> (30.9567, 22.0377)
  curve K24 (18.5535, 16.3958) -> (18.2323, 16.801)
  curve K25 (27.5945, 17.5582) -> (27.2691, 17.0568)
  curve K26 (28.1388, 17.7342) -> (27.5945, 17.5582)
  curve K27 (28.5624, 17.6359) -> (28.1388, 17.7342)
  curve K28 (28.8632, 17.3556) -> (28.5624, 17.6359)
  curve K29 (29.0495, 16.9095) -> (28.8632, 17.3556)
  curve K30 (20.5447, 16.8481) -> (20.1252, 16.9443)
  curve K31 (32.9867, 22.3181) -> (32.5631, 22.4163)
  curve K32 (33.2875, 22.0377) -> (32.9867, 22.3181)
  curve K33 (33.4737, 21.5916) -> (33.2875, 22.0377)
  curve K34 (21.9199, 15.1148) -> (21.7214, 15.5404)
  curve K35 (29.3625, 21.7389) -> (29.2541, 20.8836)
  curve K36 (27.2691, 17.0568) -> (27.1606, 16.2014)
  curve K37 (31.1941, 17.3556) -> (30.8932, 17.6359)
  curve K38 (31.3803, 16.9095) -> (31.1941, 17.3556)
  curve K39 (29.5999, 17.0568) -> (29.4915, 16.2014)
  curve K40 (29.9253, 17.5582) -> (29.5999, 17.0568)
  curve K41 (30.4696, 17.7342) -> (29.9253, 17.5582)
  curve K42 (30.8932, 17.6359) -> (30.4696, 17.7342)
  curve K43 (17.3789, 16.8604) -> (17.1108, 16.6128)
  curve K44 (17.7411, 16.9443) -> (17.3789, 16.8604)
  curve K45 (18.2323, 16.801) -> (17.7411, 16.9443)
  curve K46 (22.3905, 16.711) -> (21.8237, 16.5227)
  curve K47 (23.0535, 16.4388) -> (22.3905, 16.711)
  curve K48 (23.3237, 15.7389) -> (23.0535, 16.4388)
  curve K49 (23.0863, 15.035) -> (23.3237, 15.7389)
  curve K50 (22.2984, 14.6707) -> (23.0863, 15.035)
  curve K51 (21.6293, 14.8999) -> (22.2984, 14.6707)
  curve K52 (21.3346, 15.5077) -> (21.6293, 14.8999)
  curve K53 (23.7739, 17.0568) -> (23.6654, 16.2014)
  curve K54 (24.0992, 17.5582) -> (23.7739, 17.0568)
  curve K55 (24.6436, 17.7342) -> (24.0992, 17.5582)
  curve K56 (25.0672, 17.6359) -> (24.6436, 17.7342)
  curve K57 (31.6934, 21.7389) -> (31.5849, 20.8836)
  curve K58 (32.0188, 22.2403) -> (31.6934, 21.7389)
  curve K59 (32.5631, 22.4163) -> (32.0188, 22.2403)
  curve K60 (26.1108, 22.1932) -> (25.8755, 21.6428)
  curve K61 (26.737, 22.4163) -> (26.1108, 22.1932)
  curve K62 (26.7432, 19.3529) -> (27.4594, 19.6148)
  curve K63 (26.0269, 19.6148) -> (26.7432, 19.3529)
  curve K64 (25.7548, 20.2717) -> (26.0269, 19.6148)
  curve K65 (25.9021, 20.7608) -> (25.7548, 20.2717)
  curve K66 (26.3257, 21.0309) -> (25.9021, 20.7608)
  line L40 (24.9771, 19.404) -> (24.9771, 20.1223)
  line L41 (24.9771, 22.404) -> (24.6763, 22.404)
  line L42 (25.3823, 20.1223) -> (25.3823, 20.46)
  line L43 (24.9771, 20.1223) -> (25.3823, 20.1223)
  line L44 (28.2964, 19.8235) -> (28.2964, 19.404)
  line L45 (28.7159, 19.8235) -> (28.2964, 19.8235)
  curve K67 (31.4478, 16.2014) -> (31.3803, 16.9095)
  curve K68 (31.3394, 15.3481) -> (31.4478, 16.2014)
  curve K69 (31.014, 14.8467) -> (31.3394, 15.3481)
  curve K70 (30.4696, 14.6707) -> (31.014, 14.8467)
  line L46 (16.7752, 16.8952) -> (16.7752, 13.889)
  curve K71 (18.662, 15.8249) -> (18.5535, 16.3958)
  curve K72 (18.5413, 15.2233) -> (18.662, 15.8249)
  curve K73 (18.1934, 14.814) -> (18.5413, 15.2233)
  curve K74 (17.7145, 14.6728) -> (18.1934, 14.814)
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  dimension "d239" Text1-Height = 3
sketch "Sketch4" plane through (40, 0, 0) normal (1, 0, 0) x axis (0, 1, 0)
  line L1 (44.7318, 53.9359) -> (48.9918, 53.9359)
  line L2 (44.7318, 45.6759) -> (44.7318, 53.9359)
  line L3 (48.9918, 45.6759) -> (44.7318, 45.6759)
  line L4 (48.9918, 47.1259) -> (48.9918, 45.6759)
  line L5 (55.6118, 47.1259) -> (48.9918, 47.1259)
  line L6 (55.6118, 52.4859) -> (55.6118, 47.1259)
  line L7 (48.9918, 52.4859) -> (55.6118, 52.4859)
  line L8 (48.9918, 53.9359) -> (48.9918, 52.4859)
  circle C1 centre (44.7318, 49.8059) radius 0.85
  point P10 (44.7318, 49.8059)
  midpoint L2 P10
  dimension "d241" diameter C1 = 1.7 (= "filament_hole_width")
extrude "Extrude4" cut sketch "Sketch4" profile of L2 C1 no distance stored
sketch "Sketch15" plane through (-4, 0, 0) normal (-1, 0, 0) x axis (0, -1, 0)
  line L1 (-19.6118, 60) -> (-19.6118, 23.2332)
  line L2 (-39.6118, 60) -> (-19.6118, 60)
  line L3 (-39.6118, 52.6059) -> (-39.6118, 60)
  line L4 (-33.1118, 52.6059) -> (-39.6118, 52.6059)
  line L5 (-33.1118, 54.0559) -> (-33.1118, 52.6059)
  line L6 (-28.6118, 54.0559) -> (-33.1118, 54.0559)
  line L7 (-28.6118, 45.5559) -> (-28.6118, 54.0559)
  line L8 (-33.1118, 45.5559) -> (-28.6118, 45.5559)
  line L9 (-33.1118, 47.0059) -> (-33.1118, 45.5559)
  line L10 (-39.6118, 47.0059) -> (-33.1118, 47.0059)
  line L11 (-39.6118, 39.6118) -> (-39.6118, 47.0059)
  line L12 (-22.1725, 22.1725) -> (-39.6118, 39.6118)
  arc A1 centre (-21.1118, 23.2332) radius 1.5 clockwise from (-19.6118, 23.2332) to (-22.1725, 22.1725)
  circle C1 centre (-28.6118, 49.8059) radius 0.85
  point P16 (-28.6118, 49.8059)
  midpoint L7 P16
  dimension "d244" diameter C1 = 1.7 (= "filament_hole_width")
sketch "Sketch9" plane through (48, 0, 0) normal (1, 0, 0) x axis (0, 1, 0)
  line L1 (49.1118, 47.0059) -> (55.6118, 47.0059)
  line L2 (49.1118, 45.5559) -> (49.1118, 47.0059)
  line L3 (44.6118, 45.5559) -> (49.1118, 45.5559)
  line L4 (44.6118, 54.0559) -> (44.6118, 45.5559)
  line L5 (49.1118, 54.0559) -> (44.6118, 54.0559)
  line L6 (49.1118, 52.6059) -> (49.1118, 54.0559)
  line L7 (55.6118, 52.6059) -> (49.1118, 52.6059)
  line L8 (55.6118, 47.0059) -> (55.6118, -10)
  line L9 (39.6118, 60) -> (55.6118, 60)
  line L10 (39.6118, 52.4859) -> (39.6118, 60)
  line L11 (32.9918, 52.4859) -> (39.6118, 52.4859)
  line L12 (32.9918, 53.9359) -> (32.9918, 52.4859)
  line L13 (28.7318, 53.9359) -> (32.9918, 53.9359)
  line L14 (28.7318, 45.6759) -> (28.7318, 53.9359)
  line L15 (32.9918, 45.6759) -> (28.7318, 45.6759)
  line L16 (32.9918, 47.1259) -> (32.9918, 45.6759)
  line L17 (39.6118, 47.1259) -> (32.9918, 47.1259)
  line L18 (55.6118, 60) -> (55.6118, 52.6059)
  line L19 (39.6118, -10) -> (39.6118, 47.1259)
  line L20 (55.6118, -10) -> (39.6118, -10)
  circle C1 centre (28.7318, 49.8059) radius 0.85
  circle C2 centre (44.6118, 49.8059) radius 0.85
  point P20 (28.7318, 49.8059)
  point P21 (44.6118, 49.8059)
  midpoint L14 P20
  midpoint L4 P21
  dimension "d247" diameter C1 = 1.7 (= "filament_hole_width")
  dimension "d250" diameter C2 = 1.7 (= "filament_hole_width")
extrude "Extrude12" cut sketch "Sketch9" profile of L4 L14 C1 C2 no distance stored
sketch "Sketch16" plane through (0, 19.6118, 0) normal (0, -1, 0) x axis (1, 0, 0)
  dimension "d253" = 3
extrude "Extrude22" cut sketch "Sketch16" against normal blind 2
extrude "Extrude23" cut sketch "Sketch15" profile of L7 C1 against normal blind 260 and along normal blind 80
sketch "Sketch17" plane through (0, 19.6118, 0) normal (0, -1, 0) x axis (1, 0, 0)
  dimension "d258" = 3
extrude "Extrude24" cut sketch "Sketch17" against normal blind 2
extrude "Extrude26" cut sketch "Text" against normal blind 2
extrude "Extrude27" cut sketch "Text" against normal blind 2
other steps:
create_component "CreateComponent1"
create_component "CreateComponent2"
create_component "CreateComponent3"
create_component "CreateComponent4"
named bodies: "Wall anchor part", "Base plate with slot"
